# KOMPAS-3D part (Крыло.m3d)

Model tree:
1. Эскиз:1
2. Смещенная плоскость:1
     Расстояние = 390
3. Эскиз:3
4. Операция по сечениям:1
     Толщина стенки 1 = 1; Толщина стенки 2 = 3

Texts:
  POLYLINE_STYLE_0.18_RGB_0_0_0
